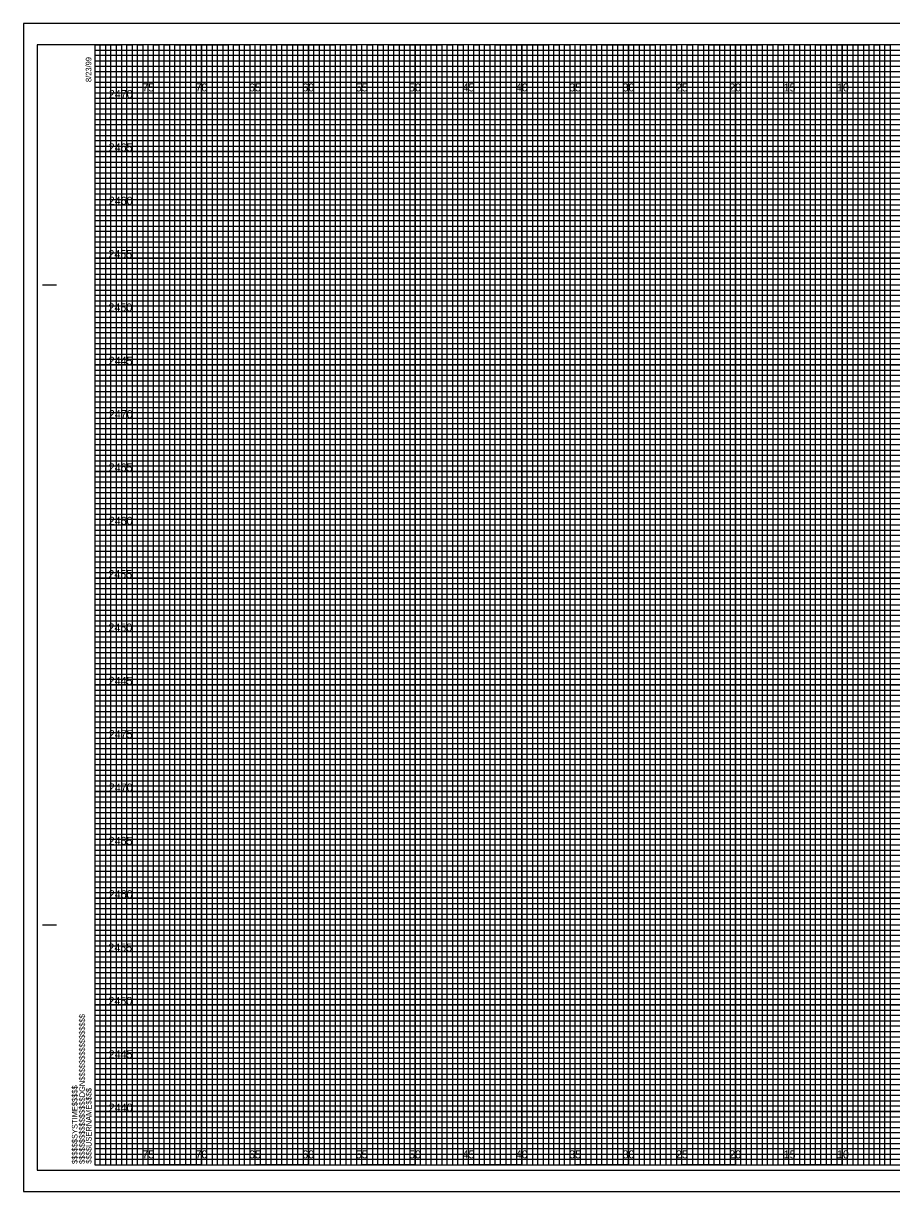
# Model space of a CAD drawing. Extents: x -7 to 162, y -2 to 107.
# Drawn here: x -6.7 to 74.6, y -2.5 to 107 of the extents above; entities that cross this region are included whole.
import ezdxf

# ---------------------------------------------------------------- set-up
doc = ezdxf.new("R2010")
doc.units = 0
for name, color, linetype in [('Exist Cross Section Cell', 7, 'Continuous'), ('Exist XS Ground Line', 7, 'Continuous'), ('Prop CMT Pvmt Course 1 Wedge', 7, 'Continuous'), ('Prop CMT Pvmt Surface', 7, 'Continuous'), ('Prop CMT Shld Paved Course 2', 7, 'Continuous'), ('Prop CMT Shld Paved Course 3', 7, 'Continuous'), ('Prop CMT Slope Grass', 7, 'Continuous'), ('Prop CMT Subgrade Earthwork', 7, 'Continuous'), ('Prop XS EOT Tick Mark', 7, 'Continuous'), ('Scratch_Level_0', 7, 'Continuous'), ('Scratch_Level_1', 7, 'Continuous')]:
    doc.layers.add(name, color=color, linetype=linetype)

msp = doc.modelspace()

# ---------------------------------------------------------------- linework, layer by layer
at = {"layer": 'Exist XS Ground Line'}
for p, q in [((5, 105), (0, 105)), ((5, 0), (5, 105)), ((15, 105), (10, 105)), ((10, 105), (10, 0)), ((15, 0), (15, 105)), ((25, 105), (20, 105)), ((20, 105), (20, 0)), ((25, 0), (25, 105)), ((35, 105), (30, 105)), ((30, 105), (30, 0)), ((35, 0), (35, 105)), ((45, 105), (40, 105)), ((40, 105), (40, 0)), ((45, 0), (45, 105)), ((55, 105), (50, 105)), ((50, 105), (50, 0)), ((55, 0), (55, 105)), ((65, 105), (60, 105)), ((60, 105), (60, 0)), ((65, 0), (65, 105)), ((75, 105), (70, 105)), ((70, 105), (70, 0)), ((10, 0), (5, 0)), ((20, 0), (15, 0)), ((30, 0), (25, 0)), ((40, 0), (35, 0)), ((50, 0), (45, 0)), ((60, 0), (55, 0)), ((70, 0), (65, 0))]:
    msp.add_line(p, q, dxfattribs=at)
for points in [[(0, 100), (160, 100), (160, 95), (0, 95)], [(0, 90), (160, 90), (160, 85), (0, 85)], [(0, 80), (160, 80), (160, 75), (0, 75)], [(0, 70), (160, 70), (160, 65), (0, 65)], [(0, 60), (160, 60), (160, 55), (0, 55)], [(0, 50), (160, 50), (160, 45), (0, 45)], [(0, 40), (160, 40), (160, 35), (0, 35)], [(0, 30), (160, 30), (160, 25), (0, 25)], [(0, 20), (160, 20), (160, 15), (0, 15)], [(0, 10), (160, 10), (160, 5), (0, 5)]]:
    msp.add_lwpolyline(points, dxfattribs=at)
at = {"layer": 'Prop CMT Pvmt Course 1 Wedge'}
for p, q in [((5, 0), (5, 105)), ((10, 0), (10, 105)), ((15, 0), (15, 105)), ((20, 0), (20, 105)), ((25, 0), (25, 105)), ((30, 0), (30, 105)), ((35, 0), (35, 105)), ((40, 0), (40, 105)), ((45, 0), (45, 105)), ((50, 0), (50, 105)), ((55, 0), (55, 105)), ((60, 0), (60, 105)), ((65, 0), (65, 105)), ((70, 0), (70, 105)), ((0, 100), (160, 100)), ((0, 95), (160, 95)), ((0, 90), (160, 90)), ((0, 85), (160, 85)), ((0, 80), (160, 80)), ((0, 75), (160, 75)), ((0, 70), (160, 70)), ((0, 65), (160, 65)), ((0, 60), (160, 60)), ((0, 55), (160, 55)), ((0, 50), (160, 50)), ((0, 45), (160, 45)), ((0, 40), (160, 40)), ((0, 35), (160, 35)), ((0, 30), (160, 30)), ((0, 25), (160, 25)), ((0, 20), (160, 20)), ((0, 15), (160, 15)), ((0, 10), (160, 10)), ((0, 5), (160, 5))]:
    msp.add_line(p, q, dxfattribs=at)
at = {"layer": 'Prop CMT Shld Paved Course 2'}
msp.add_lwpolyline([(-6.7, -2.5), (161.65, -2.5), (161.65, 107), (-6.7, 107)], close=True, dxfattribs=at)
at = {"layer": 'Prop CMT Shld Paved Course 3'}
msp.add_lwpolyline([(-5.4, -0.5), (161.2, -0.5), (161.2, 105), (-5.4, 105)], close=True, dxfattribs=at)
at = {"layer": 'Prop CMT Slope Grass'}
for points in [[(0, 0), (0.5, 0), (0.5, 105), (1, 105), (1, 0)], [(1, 0), (1.5, 0), (1.5, 105), (2, 105), (2, 0)], [(2.5, 0), (3, 0), (3, 105), (3.5, 105), (3.5, 0)], [(3.5, 0), (4, 0), (4, 105), (4.5, 105), (4.5, 0)], [(5, 0), (5.5, 0), (5.5, 105), (6, 105), (6, 0)], [(6, 0), (6.5, 0), (6.5, 105), (7, 105), (7, 0)], [(7.5, 0), (8, 0), (8, 105), (8.5, 105), (8.5, 0)], [(8.5, 0), (9, 0), (9, 105), (9.5, 105), (9.5, 0)], [(10, 0), (10.5, 0), (10.5, 105), (11, 105), (11, 0)], [(11, 0), (11.5, 0), (11.5, 105), (12, 105), (12, 0)], [(12.5, 0), (13, 0), (13, 105), (13.5, 105), (13.5, 0)], [(13.5, 0), (14, 0), (14, 105), (14.5, 105), (14.5, 0)], [(15, 0), (15.5, 0), (15.5, 105), (16, 105), (16, 0)], [(16, 0), (16.5, 0), (16.5, 105), (17, 105), (17, 0)], [(17.5, 0), (18, 0), (18, 105), (18.5, 105), (18.5, 0)], [(18.5, 0), (19, 0), (19, 105), (19.5, 105), (19.5, 0)], [(20, 0), (20.5, 0), (20.5, 105), (21, 105), (21, 0)], [(21, 0), (21.5, 0), (21.5, 105), (22, 105), (22, 0)], [(22.5, 0), (23, 0), (23, 105), (23.5, 105), (23.5, 0)], [(23.5, 0), (24, 0), (24, 105), (24.5, 105), (24.5, 0)], [(25, 0), (25.5, 0), (25.5, 105), (26, 105), (26, 0)], [(26, 0), (26.5, 0), (26.5, 105), (27, 105), (27, 0)], [(27.5, 0), (28, 0), (28, 105), (28.5, 105), (28.5, 0)], [(28.5, 0), (29, 0), (29, 105), (29.5, 105), (29.5, 0)], [(30, 0), (30.5, 0), (30.5, 105), (31, 105), (31, 0)], [(31, 0), (31.5, 0), (31.5, 105), (32, 105), (32, 0)], [(32.5, 0), (33, 0), (33, 105), (33.5, 105), (33.5, 0)], [(33.5, 0), (34, 0), (34, 105), (34.5, 105), (34.5, 0)], [(35, 0), (35.5, 0), (35.5, 105), (36, 105), (36, 0)], [(36, 0), (36.5, 0), (36.5, 105), (37, 105), (37, 0)], [(37.5, 0), (38, 0), (38, 105), (38.5, 105), (38.5, 0)], [(38.5, 0), (39, 0), (39, 105), (39.5, 105), (39.5, 0)], [(40, 0), (40.5, 0), (40.5, 105), (41, 105), (41, 0)], [(41, 0), (41.5, 0), (41.5, 105), (42, 105), (42, 0)], [(42.5, 0), (43, 0), (43, 105), (43.5, 105), (43.5, 0)], [(43.5, 0), (44, 0), (44, 105), (44.5, 105), (44.5, 0)], [(45, 0), (45.5, 0), (45.5, 105), (46, 105), (46, 0)], [(46, 0), (46.5, 0), (46.5, 105), (47, 105), (47, 0)], [(47.5, 0), (48, 0), (48, 105), (48.5, 105), (48.5, 0)], [(48.5, 0), (49, 0), (49, 105), (49.5, 105), (49.5, 0)], [(50, 0), (50.5, 0), (50.5, 105), (51, 105), (51, 0)], [(51, 0), (51.5, 0), (51.5, 105), (52, 105), (52, 0)], [(52.5, 0), (53, 0), (53, 105), (53.5, 105), (53.5, 0)], [(53.5, 0), (54, 0), (54, 105), (54.5, 105), (54.5, 0)], [(55, 0), (55.5, 0), (55.5, 105), (56, 105), (56, 0)], [(56, 0), (56.5, 0), (56.5, 105), (57, 105), (57, 0)], [(57.5, 0), (58, 0), (58, 105), (58.5, 105), (58.5, 0)], [(58.5, 0), (59, 0), (59, 105), (59.5, 105), (59.5, 0)], [(60, 0), (60.5, 0), (60.5, 105), (61, 105), (61, 0)], [(61, 0), (61.5, 0), (61.5, 105), (62, 105), (62, 0)], [(62.5, 0), (63, 0), (63, 105), (63.5, 105), (63.5, 0)], [(63.5, 0), (64, 0), (64, 105), (64.5, 105), (64.5, 0)], [(65, 0), (65.5, 0), (65.5, 105), (66, 105), (66, 0)], [(66, 0), (66.5, 0), (66.5, 105), (67, 105), (67, 0)], [(67.5, 0), (68, 0), (68, 105), (68.5, 105), (68.5, 0)], [(68.5, 0), (69, 0), (69, 105), (69.5, 105), (69.5, 0)], [(70, 0), (70.5, 0), (70.5, 105), (71, 105), (71, 0)], [(71, 0), (71.5, 0), (71.5, 105), (72, 105), (72, 0)], [(72.5, 0), (73, 0), (73, 105), (73.5, 105), (73.5, 0)], [(73.5, 0), (74, 0), (74, 105), (74.5, 105), (74.5, 0)]]:
    msp.add_lwpolyline(points, dxfattribs=at)
at = {"layer": 'Prop CMT Subgrade Earthwork'}
for p, q in [((161.65, 107), (-6.7, 107)), ((-6.7, 107), (-6.7, -2.5)), ((-6.7, -2.5), (161.65, -2.5))]:
    msp.add_line(p, q, dxfattribs=at)
at = {"layer": 'Prop XS EOT Tick Mark'}
for p, q in [((-4.9, 82.5), (-3.65, 82.5)), ((-4.85, 82.5), (-3.6, 82.5)), ((-4.9, 22.5), (-3.65, 22.5)), ((-4.85, 22.5), (-3.6, 22.5)), ((0, 0), (0, 0)), ((0, 0), (0, 0)), ((0, 0), (0, 0)), ((0, 0), (0, 0)), ((0, 0), (0, 0)), ((0, 0), (0, 0)), ((0, 0), (0, 0))]:
    msp.add_line(p, q, dxfattribs=at)
msp.add_lwpolyline([(160, 105), (0, 105), (0, 0), (160, 0)], close=True, dxfattribs=at)
at = {"layer": 'Scratch_Level_0'}
for points in [[(0, 105), (2.5, 105), (2.5, 0), (7.5, 0), (7.5, 105), (12.5, 105), (12.5, 0), (17.5, 0), (17.5, 105), (22.5, 105), (22.5, 0), (27.5, 0), (27.5, 105), (32.5, 105), (32.5, 0), (37.5, 0), (37.5, 105), (42.5, 105), (42.5, 0), (47.5, 0), (47.5, 105), (52.5, 105), (52.5, 0), (57.5, 0), (57.5, 105), (62.5, 105), (62.5, 0), (67.5, 0), (67.5, 105), (72.5, 105), (72.5, 0), (77.5, 0)], [(0, 102.5), (137.5, 102.5)], [(0, 92.5), (160, 92.5), (160, 97.5), (0, 97.5)], [(0, 82.5), (160, 82.5), (160, 87.5), (0, 87.5)], [(0, 72.5), (160, 72.5), (160, 77.5), (0, 77.5)], [(0, 62.5), (160, 62.5), (160, 67.5), (0, 67.5)], [(0, 52.5), (160, 52.5), (160, 57.5), (0, 57.5)], [(0, 42.5), (160, 42.5), (160, 47.5), (0, 47.5)], [(0, 32.5), (160, 32.5), (160, 37.5), (0, 37.5)], [(0, 22.5), (160, 22.5), (160, 27.5), (0, 27.5)], [(0, 12.5), (160, 12.5), (160, 17.5), (0, 17.5)], [(0, 2.5), (160, 2.5), (160, 7.5), (0, 7.5)]]:
    msp.add_lwpolyline(points, dxfattribs=at)
at = {"layer": 'Scratch_Level_1'}
for p, q in [((0, 104.5), (130, 104.5)), ((130, 103.99), (0, 103.99)), ((0, 103.99), (0, 103.5)), ((0, 103.5), (130, 103.5)), ((130, 102.95), (0, 102.95)), ((0, 102.95), (0, 102)), ((0, 102), (160, 102))]:
    msp.add_line(p, q, dxfattribs=at)
for points in [[(0, 101.5), (135, 101.5), (160, 101.5), (160, 101), (0, 101)], [(0, 100.5), (160, 100.5), (160, 99.5), (0, 99.5)], [(0, 99), (160, 99), (160, 98.5), (0, 98.49)], [(0, 98), (160, 98), (160, 97), (0, 97)], [(0, 96.5), (160, 96.5), (160, 96), (0, 96)], [(0, 95.5), (160, 95.5), (160, 94.5), (0, 94.5)], [(0, 94), (160, 94), (160, 93.5), (0, 93.5)], [(0, 93), (160, 93), (160, 92), (0, 92)], [(0, 91.5), (160, 91.5), (160, 91), (0, 91)], [(0, 90.5), (160, 90.5), (160, 89.5), (0, 89.5)], [(0, 89), (160, 89), (160, 88.5), (0, 88.5)], [(0, 88), (160, 88), (160, 86.98), (160, 86.5), (160, 86), (0, 86)], [(0, 87), (160, 87), (160, 86.5), (0, 86.5)], [(0, 85.5), (160, 85.5), (160, 84.5), (0, 84.52)], [(0, 84.52), (160, 84.5), (160, 84), (0, 84)], [(0, 83.5), (160, 83.5), (160, 83), (0, 83)], [(0, 82), (160, 82), (160, 81.5), (0, 81.5)], [(0, 81), (160, 81), (160, 80.5), (0, 80.5)], [(-0.04, 79.45), (160, 79.45), (160, 78.94), (-0.04, 78.94)], [(0, 78.5), (160, 78.5), (160, 78), (0, 78)], [(0, 77), (160, 77), (160, 76.5), (0, 76.5)], [(0, 76), (160, 76), (160, 75.5), (0, 75.5)], [(0, 74.5), (160, 74.5), (160, 74), (0, 74)], [(0, 73.5), (160, 73.5), (160, 73), (0, 73)], [(0, 72), (160, 72), (160, 71.5), (0, 71.5)], [(0, 71), (160, 71), (160, 70.5), (0, 70.5)], [(0, 69.5), (160, 69.5), (160, 68.99), (0, 69)], [(0, 68.5), (160, 68.5), (160, 68), (0, 68)], [(0, 67), (160, 67), (160, 66.5), (0, 66.5)], [(0, 66), (160, 66), (160, 65.5), (0, 65.5)], [(0, 64.5), (160, 64.5), (160, 64), (0, 64)], [(0, 63.5), (160, 63.5), (160, 63), (0, 63)], [(0, 62), (160, 62), (160, 61.5), (0, 61.5)], [(0, 61), (160, 61), (160, 60.5), (0, 60.5)], [(0, 59.5), (160, 59.5), (160, 59), (0, 59)], [(0, 58.5), (160.03, 58.45), (160, 58), (0, 58)], [(0, 57), (160, 57), (160, 56.5), (0, 56.5)], [(0, 56), (160, 56), (160, 55.5), (0, 55.5)], [(0, 54.5), (160, 54.5), (160, 54), (0, 54)], [(0, 53.5), (160, 53.5), (160, 53), (0, 53)], [(0, 52), (160, 52), (160, 51.5), (0, 51.5)], [(0, 51), (160, 51), (160, 50.5), (0, 50.5)], [(0, 49.5), (160, 49.5), (160, 49), (0, 49)], [(0, 48.5), (160, 48.5), (160, 48), (0, 48)], [(0, 47), (160, 47), (160, 46.5), (0, 46.5)], [(0, 46), (160, 46), (160, 45.5), (0, 45.5)], [(0, 44.5), (160, 44.5), (160, 44), (0, 44)], [(0, 43.5), (160, 43.5), (160, 43), (0, 43)], [(0, 42), (160, 42), (160, 41.5), (0, 41.5)], [(0, 41), (160, 41), (160, 40.5), (0, 40.5)], [(0, 39.5), (160, 39.5), (160, 38.99), (0, 39)], [(0, 38.5), (160, 38.5), (160, 38), (0, 38)], [(0, 37), (160, 37), (160, 36.5), (0, 36.5)], [(0, 36), (160, 36), (160, 35.5), (0, 35.5)], [(0, 34.5), (160, 34.5), (160, 34), (0, 34)], [(0, 33.5), (160, 33.5), (160, 33), (0, 33)], [(0, 32), (160, 32), (160, 31.5), (0, 31.5)], [(0, 31), (160, 31), (160, 30.5), (0, 30.5)], [(0, 29.5), (160, 29.5), (160, 29), (0, 29)], [(0, 28.5), (160.03, 28.46), (160, 28), (0, 28)], [(0, 27), (160, 27), (160, 26.5), (0, 26.5)], [(0, 26), (160, 26), (160, 25.5), (0, 25.5)], [(0, 24.5), (160, 24.5), (160, 24), (0, 24)], [(0, 23.5), (160, 23.5), (160, 23), (0, 23)], [(0, 22), (160, 22), (160, 21.5), (0, 21.5)], [(0, 21), (160, 21), (160, 20.5), (0, 20.5)], [(0, 19.5), (160, 19.5), (160, 19), (0, 19)], [(0, 18.5), (160, 18.5), (160, 18), (0, 18)], [(0, 17), (160, 17), (160, 16.5), (0, 16.5)], [(0, 16), (160, 16), (160, 15.5), (0, 15.5)], [(0, 14.5), (160, 14.5), (160, 14), (0, 14)], [(0, 13.5), (160, 13.5), (160, 13), (0, 13)], [(0, 12), (160, 12), (160, 11.5), (0, 11.5)], [(0, 11), (160, 11), (160, 10.5), (0, 10.5)], [(0, 9.5), (160, 9.5), (160, 9), (0, 9)], [(0, 8.5), (160, 8.5), (160, 8), (0, 8)], [(0, 7), (160, 7), (160, 6.5), (0, 6.5)], [(0, 6), (160, 6), (160, 5.5), (0, 5.5)], [(0, 4.5), (160, 4.5), (160, 4), (0, 4)], [(0, 3.5), (160, 3.5), (160, 3), (0, 3)], [(0, 2), (160, 2), (160, 1.5), (0, 1.5)], [(0, 1), (160, 1), (160, 0.5), (0, 0.5)]]:
    msp.add_lwpolyline(points, dxfattribs=at)

# ---------------------------------------------------------------- texts
at = {"layer": 'Exist Cross Section Cell'}
for s, p in [('75', (4.44, 100.62)), ('70', (9.43, 100.62)), ('65', (14.44, 100.62)), ('60', (19.43, 100.62)), ('55', (24.44, 100.62)), ('50', (29.43, 100.62)), ('45', (34.44, 100.62)), ('40', (39.43, 100.62)), ('35', (44.44, 100.62)), ('30', (49.43, 100.62)), ('25', (54.44, 100.62)), ('20', (59.43, 100.62)), ('15', (64.53, 100.62)), ('10', (69.52, 100.62)), ('75', (4.44, 0.62)), ('70', (9.43, 0.62)), ('65', (14.44, 0.62)), ('60', (19.43, 0.62)), ('55', (24.44, 0.62)), ('50', (29.43, 0.62)), ('45', (34.44, 0.62)), ('40', (39.43, 0.62)), ('35', (44.44, 0.62)), ('30', (49.43, 0.62)), ('25', (54.44, 0.62)), ('20', (59.43, 0.62)), ('15', (64.53, 0.62)), ('10', (69.52, 0.62))]:
    msp.add_text(s, height=0.75, dxfattribs=at).set_placement(p)
at = {"layer": 'Prop CMT Pvmt Surface'}
for s, p in [('2470', (1.31, 100)), ('2465', (1.29, 95)), ('2460', (1.3, 90)), ('2455', (1.26, 85)), ('2450', (1.27, 80)), ('2445', (1.29, 75)), ('2470', (1.31, 70)), ('2465', (1.29, 65)), ('2460', (1.3, 60)), ('2455', (1.26, 55)), ('2450', (1.27, 50)), ('2445', (1.29, 45)), ('2475', (1.3, 40)), ('2470', (1.31, 35)), ('2465', (1.29, 30)), ('2460', (1.3, 25)), ('2455', (1.26, 20)), ('2450', (1.27, 15)), ('2445', (1.29, 10)), ('2440', (1.3, 5))]:
    msp.add_text(s, height=0.75, dxfattribs=at).set_placement(p)
at = {"layer": 'Prop XS EOT Tick Mark'}
for s, p in [('8/23/99', (-0.33, 101.5)), ('$$$$$$$$$$$$$$$$DGN$$$$$$$$$$$$$$$$', (-0.94, 0.09)), ('$$$$$$SYSTIME$$$$$', (-1.63, 0.09)), ('$$$$USERNAME$$$$', (-0.31, 0.12))]:
    msp.add_text(s, height=0.525, rotation=90, dxfattribs=at).set_placement(p)

doc.saveas('drawing.dxf')
